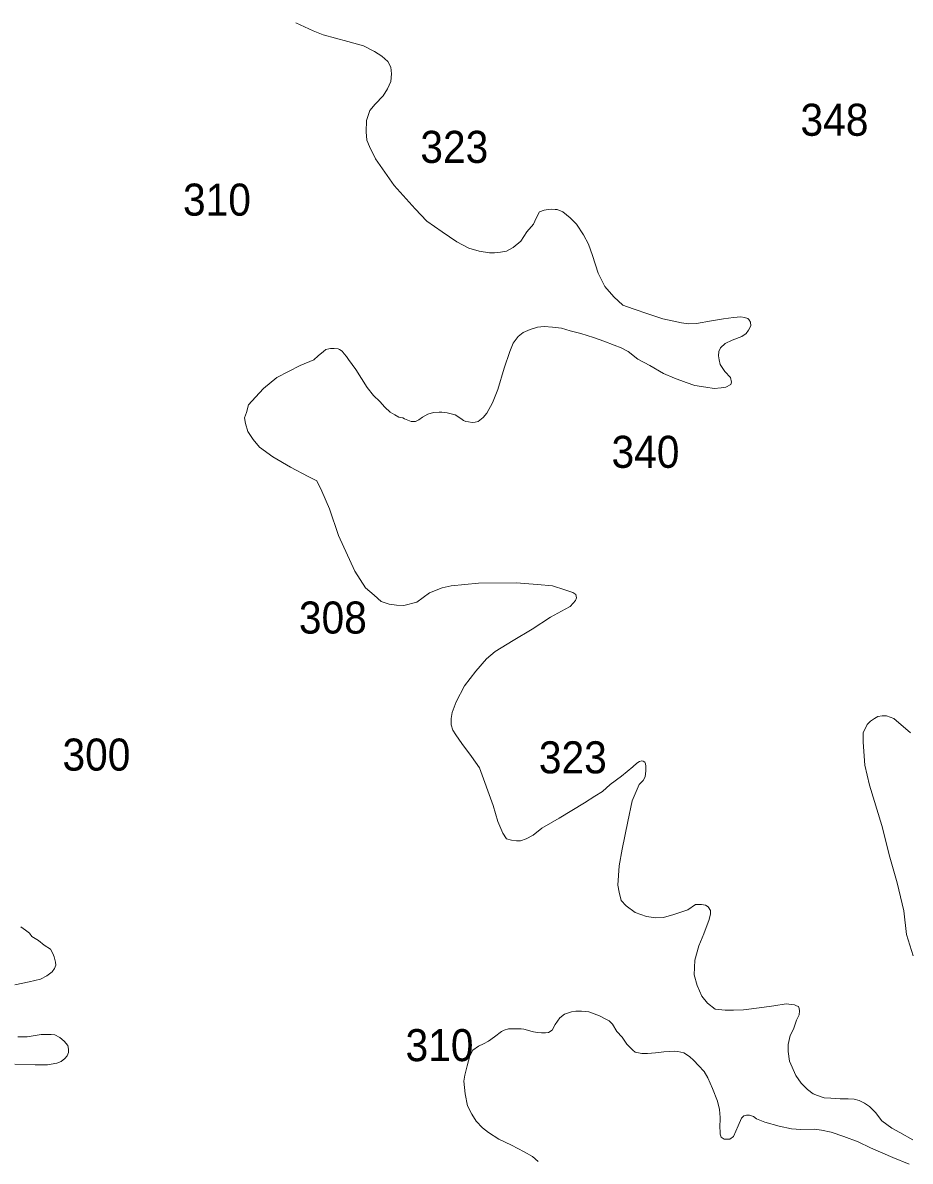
# Model space of a CAD drawing. Extents: x 445.4 to 500, y 8728.7 to 8784.
# Drawn here: x 453.35 to 457.78, y 8766.01 to 8771.69 of the extents above; entities that cross this region are included whole.
import ezdxf

# ---------------------------------------------------------------- set-up
doc = ezdxf.new("R2010")
doc.units = 0
doc.header["$LTSCALE"] = 0.064
doc.layers.add('2', color=7, linetype='Continuous', lineweight=13)
doc.layers.add('21', color=7, linetype='Continuous')

msp = doc.modelspace()

# ---------------------------------------------------------------- linework, layer by layer
at = {"layer": '2'}
for points in [[(454.7142, 8771.6898), (454.8003, 8771.6492), (454.8504, 8771.6289), (454.9725, 8771.5961), (455.0507, 8771.5742), (455.1055, 8771.5461), (455.1431, 8771.5227), (455.1728, 8771.4961), (455.1885, 8771.468), (455.1916, 8771.4352)], [(455.1916, 8771.4352), (455.1885, 8771.3961), (455.1713, 8771.3591), (455.1494, 8771.3247), (455.1087, 8771.2841), (455.0821, 8771.2513), (455.0664, 8771.2013), (455.0648, 8771.145), (455.068, 8771.1044), (455.0805, 8771.0716), (455.1108, 8771.0099), (455.2047, 8770.8771), (455.3096, 8770.7615), (455.3676, 8770.6995), (455.4443, 8770.6464), (455.5179, 8770.5964), (455.5773, 8770.5651), (455.629, 8770.5495), (455.6807, 8770.5417), (455.7057, 8770.5417), (455.7354, 8770.5448), (455.7652, 8770.5495), (455.799, 8770.5675), (455.8366, 8770.5988), (455.8663, 8770.6456), (455.8992, 8770.6847), (455.9133, 8770.7144), (455.9305, 8770.7456), (455.9524, 8770.755), (455.9727, 8770.7581), (455.9915, 8770.7597), (456.0072, 8770.7581), (456.0181, 8770.7581), (456.0463, 8770.7456), (456.0823, 8770.7159), (456.1152, 8770.6847), (456.1499, 8770.6319), (456.175, 8770.585), (456.1938, 8770.5272), (456.2235, 8770.4397), (456.2564, 8770.3741), (456.3002, 8770.321), (456.3456, 8770.2804), (456.3972, 8770.2616), (456.4749, 8770.2354), (456.5447, 8770.2112), (456.6387, 8770.1913), (456.6758, 8770.187), (456.7143, 8770.1885), (456.7884, 8770.2013), (456.8482, 8770.2112), (456.8981, 8770.2183), (456.9351, 8770.2212), (456.9537, 8770.2183), (456.9693, 8770.2141), (456.975, 8770.2084), (456.9836, 8770.1956), (456.9843, 8770.1762), (456.9734, 8770.1559), (456.9608, 8770.1387), (456.9405, 8770.1231), (456.892, 8770.1059), (456.856, 8770.0887), (456.8341, 8770.0668), (456.8247, 8770.0496), (456.8231, 8770.0278), (456.8262, 8770.0075), (456.8309, 8769.984), (456.8544, 8769.9497), (456.8826, 8769.9184), (456.8888, 8769.8965), (456.8841, 8769.884), (456.8607, 8769.8715), (456.8372, 8769.8669), (456.8012, 8769.8637), (456.7605, 8769.8715), (456.7057, 8769.8794), (456.6619, 8769.8934), (456.604, 8769.9153), (456.5492, 8769.9387), (456.4803, 8769.9793), (456.4208, 8770.0106), (456.3723, 8770.0481), (456.3382, 8770.0664), (456.3022, 8770.0805), (456.2505, 8770.1008), (456.1989, 8770.1195), (456.1363, 8770.1383), (456.0831, 8770.1524), (456.0392, 8770.1648), (455.9939, 8770.1711), (455.9532, 8770.1742), (455.9203, 8770.1711), (455.8827, 8770.1586), (455.8483, 8770.143), (455.8232, 8770.1242), (455.7982, 8770.0899), (455.781, 8770.0492), (455.7528, 8769.9649), (455.7215, 8769.8587), (455.6949, 8769.793)], [(455.6949, 8769.793), (455.6672, 8769.7414), (455.6491, 8769.7203), (455.624, 8769.7003), (455.608, 8769.6963), (455.593, 8769.6953), (455.5759, 8769.6973), (455.5619, 8769.7003), (455.5508, 8769.7053), (455.5438, 8769.7093), (455.5318, 8769.7173), (455.5087, 8769.7323), (455.4686, 8769.7434), (455.4425, 8769.7464), (455.4295, 8769.7464), (455.4014, 8769.7444), (455.3723, 8769.7353), (455.3453, 8769.7213), (455.3272, 8769.7073), (455.3112, 8769.7003), (455.2961, 8769.6993), (455.2891, 8769.6993), (455.265, 8769.7093), (455.256, 8769.7133), (455.247, 8769.7173), (455.2269, 8769.7213), (455.2069, 8769.7323), (455.1838, 8769.7464), (455.1577, 8769.771), (455.1332, 8769.7998), (455.1013, 8769.8295), (455.0693, 8769.87), (455.0128, 8769.9593), (454.9766, 8770.0082), (454.9659, 8770.0231), (454.9553, 8770.037), (454.9446, 8770.0508), (454.9318, 8770.0593), (454.9243, 8770.0614), (454.9041, 8770.0636), (454.8966, 8770.0646), (454.886, 8770.0646), (454.8775, 8770.0625), (454.8636, 8770.0582), (454.8519, 8770.0497), (454.8258, 8770.0276), (454.8031, 8770.0074), (454.7349, 8769.9797), (454.6186, 8769.9192), (454.5529, 8769.8637), (454.5125, 8769.8208), (454.4771, 8769.783), (454.467, 8769.7451), (454.4569, 8769.7174), (454.4619, 8769.6896), (454.4746, 8769.6493), (454.4998, 8769.6089), (454.5327, 8769.5711), (454.5984, 8769.5238), (454.6869, 8769.4709), (454.7753, 8769.4255), (454.8183, 8769.4028), (454.8436, 8769.3523), (454.8815, 8769.264), (454.927, 8769.1304), (455.008, 8768.9519), (455.0611, 8768.8687), (455.104, 8768.8334), (455.1394, 8768.8006), (455.1798, 8768.788), (455.2152, 8768.783), (455.2531, 8768.7804), (455.3177, 8768.7985), (455.3809, 8768.8439), (455.4441, 8768.8691), (455.4896, 8768.8792), (455.626, 8768.8918), (455.813, 8768.8943), (455.9192, 8768.8867), (455.995, 8768.8792), (456.0556, 8768.859), (456.0961, 8768.8464), (456.1112, 8768.8363), (456.1137, 8768.8186), (456.1087, 8768.806), (456.0986, 8768.7934), (456.0834, 8768.7758), (456.0581, 8768.7631), (455.9849, 8768.7228), (455.8939, 8768.6623), (455.7979, 8768.6068), (455.7088, 8768.552), (455.6658, 8768.5142), (455.6128, 8768.4536), (455.5547, 8768.3805), (455.5142, 8768.2998), (455.494, 8768.2468), (455.4889, 8768.2166), (455.4889, 8768.1863), (455.4965, 8768.1585), (455.5117, 8768.1358)], [(457.7811, 8768.1449), (457.6989, 8768.2179), (457.6624, 8768.2301), (457.6396, 8768.2301), (457.6183, 8768.227), (457.6015, 8768.2179), (457.5817, 8768.2042), (457.565, 8768.1875), (457.5452, 8768.1449), (457.5452, 8768.0993), (457.5543, 8767.9838), (457.5773, 8767.8837), (457.6382, 8767.683), (457.6778, 8767.5249), (457.7144, 8767.3975), (457.7478, 8767.2576), (457.7615, 8767.139), (457.795, 8767.0326)], [(455.5117, 8768.1358), (455.542, 8768.093), (455.5902, 8768.0282), (455.6307, 8767.9702), (455.6989, 8767.7836), (455.7216, 8767.7029), (455.7469, 8767.6449), (455.7646, 8767.6171), (455.7899, 8767.6095), (455.8151, 8767.607), (455.8353, 8767.607), (455.8631, 8767.6171), (455.8985, 8767.6348), (455.9415, 8767.6701), (456.0274, 8767.7205), (456.1552, 8767.7959), (456.2053, 8767.8292), (456.245, 8767.8523), (456.2822, 8767.8881), (456.3387, 8767.9291), (456.3951, 8767.9752), (456.4156, 8767.9944), (456.4297, 8768.0033), (456.44, 8768.0059), (456.4477, 8768.0046), (456.4554, 8767.9995), (456.4592, 8767.9905), (456.4605, 8767.979), (456.4605, 8767.956), (456.4569, 8767.9252), (456.447, 8767.9079), (456.4272, 8767.8881), (456.3925, 8767.8066), (456.3702, 8767.7028), (456.343, 8767.5655), (456.3281, 8767.4815), (456.3207, 8767.3852), (456.3281, 8767.3506), (456.338, 8767.3086), (456.3628, 8767.2814), (456.4073, 8767.2493), (456.4643, 8767.2295), (456.5113, 8767.2221), (456.5484, 8767.2246), (456.6004, 8767.2394), (456.6697, 8767.2616), (456.7093, 8767.2888), (456.739, 8767.2888), (456.7588, 8767.2863), (456.7712, 8767.2765), (456.7835, 8767.2592), (456.7835, 8767.2419), (456.7761, 8767.2147), (456.7494, 8767.142), (456.7247, 8767.0828), (456.7049, 8767.0111), (456.7024, 8766.937), (456.7172, 8766.8851), (456.7395, 8766.8308), (456.7692, 8766.7962), (456.8064, 8766.7666), (456.8566, 8766.7606), (456.8986, 8766.7606), (456.9481, 8766.7631), (457.0397, 8766.7754), (457.0991, 8766.7828), (457.161, 8766.7927), (457.2031, 8766.7878), (457.213, 8766.7828), (457.2229, 8766.7804), (457.2253, 8766.7705), (457.2278, 8766.7581), (457.2253, 8766.7384), (457.213, 8766.7112), (457.1981, 8766.6667), (457.1808, 8766.6346), (457.1709, 8766.5902), (457.1709, 8766.5556), (457.1783, 8766.5062), (457.2102, 8766.4351), (457.2358, 8766.3968), (457.2671, 8766.3656), (457.2955, 8766.3443), (457.3168, 8766.3358), (457.351, 8766.3244), (457.3837, 8766.3216), (457.4306, 8766.3187), (457.4705, 8766.3187), (457.5003, 8766.3173), (457.5259, 8766.3102), (457.5515, 8766.2974), (457.5771, 8766.2804), (457.607, 8766.2506), (457.6391, 8766.2098), (457.688, 8766.1718), (457.7287, 8766.1501), (457.7938, 8766.1149)], [(453.311, 8766.8879), (453.3821, 8766.9028), (453.4381, 8766.9158), (453.4703, 8766.9335), (453.4964, 8766.9522), (453.5095, 8766.969), (453.5151, 8766.9858), (453.5133, 8767.0007), (453.5077, 8767.0268), (453.5002, 8767.0436), (453.489, 8767.066), (453.4576, 8767.0854), (453.4293, 8767.1089), (453.3963, 8767.1293), (453.3838, 8767.145), (453.3633, 8767.1607), (453.3414, 8767.1779)], [(457.7748, 8765.993), (457.6934, 8766.0255), (457.5821, 8766.0743), (457.52, 8766.1039), (457.4483, 8766.1304), (457.3859, 8766.1521), (457.3376, 8766.163), (457.3033, 8766.1677), (457.2346, 8766.1662), (457.1878, 8766.1693), (457.127, 8766.1817), (457.0553, 8766.202), (457.0132, 8766.2191), (456.9976, 8766.2315), (456.9789, 8766.2378), (456.9633, 8766.2378), (456.9492, 8766.2346), (456.9383, 8766.2222), (456.9212, 8766.1833), (456.8978, 8766.1304), (456.8806, 8766.1179), (456.851, 8766.1179), (456.8369, 8766.1272), (456.8323, 8766.1428), (456.8323, 8766.1584), (456.8307, 8766.1724), (456.8323, 8766.2253), (456.8276, 8766.2658), (456.818, 8766.3074), (456.794, 8766.3705), (456.7701, 8766.4233), (456.7513, 8766.4557), (456.724, 8766.4847), (456.7001, 8766.5103), (456.6779, 8766.5307), (456.6506, 8766.5478), (456.6198, 8766.5546), (456.6027, 8766.5563), (456.5805, 8766.5546), (456.5498, 8766.5529), (456.5088, 8766.5478), (456.4695, 8766.5444), (456.4405, 8766.5444), (456.408, 8766.5512), (456.396, 8766.5614), (456.3655, 8766.5911), (456.3432, 8766.6264), (456.3157, 8766.6552), (456.2934, 8766.6918), (456.2777, 8766.7088), (456.258, 8766.718), (456.2292, 8766.7324), (456.1754, 8766.7533), (456.14, 8766.7559), (456.1112, 8766.7559), (456.0889, 8766.7533), (456.0548, 8766.7416), (456.0312, 8766.7232), (456.0083, 8766.6898), (455.9938, 8766.6623), (455.9755, 8766.6493), (455.9597, 8766.6479), (455.9401, 8766.6479), (455.9191, 8766.6493), (455.8994, 8766.6532), (455.8863, 8766.6571), (455.8693, 8766.661), (455.8522, 8766.6663), (455.8378, 8766.6676), (455.8168, 8766.6689), (455.7932, 8766.6689), (455.7749, 8766.6676), (455.7539, 8766.6623), (455.7408, 8766.6545), (455.7054, 8766.6283), (455.6752, 8766.6061), (455.6503, 8766.593), (455.6254, 8766.5812), (455.5965, 8766.5616), (455.5821, 8766.5328), (455.5686, 8766.4842), (455.5563, 8766.4363), (455.5526, 8766.4068), (455.5588, 8766.3432), (455.5711, 8766.2843), (455.5921, 8766.2425), (455.6142, 8766.2068), (455.645, 8766.1749), (455.6758, 8766.1503), (455.7266, 8766.1175), (455.7894, 8766.0868), (455.8534, 8766.0548), (455.8941, 8766.0303), (455.9224, 8766.0057)], [(453.311, 8766.4914), (453.412, 8766.4886), (453.4737, 8766.4886), (453.5204, 8766.4961), (453.5428, 8766.5054), (453.5596, 8766.5203), (453.5727, 8766.5334), (453.5783, 8766.5502), (453.5783, 8766.567), (453.5746, 8766.5856), (453.5578, 8766.6062), (453.5353, 8766.6248), (453.511, 8766.6379), (453.4923, 8766.6397), (453.4419, 8766.6397), (453.3727, 8766.6285), (453.326, 8766.6285)]]:
    msp.add_lwpolyline(points, dxfattribs=at)

# ---------------------------------------------------------------- texts
at = {"layer": '21', "width": 0.95}
for s, p in [('348', (457.2326, 8771.1255)), ('323', (455.335, 8770.9902)), ('310', (454.1503, 8770.7269)), ('340', (456.2893, 8769.4682)), ('308', (454.7288, 8768.6411)), ('300', (453.5486, 8767.957)), ('323', (455.9267, 8767.9434)), ('310', (455.2611, 8766.5069))]:
    msp.add_text(s, height=0.16, dxfattribs=at).set_placement(p)

doc.saveas('drawing.dxf')
